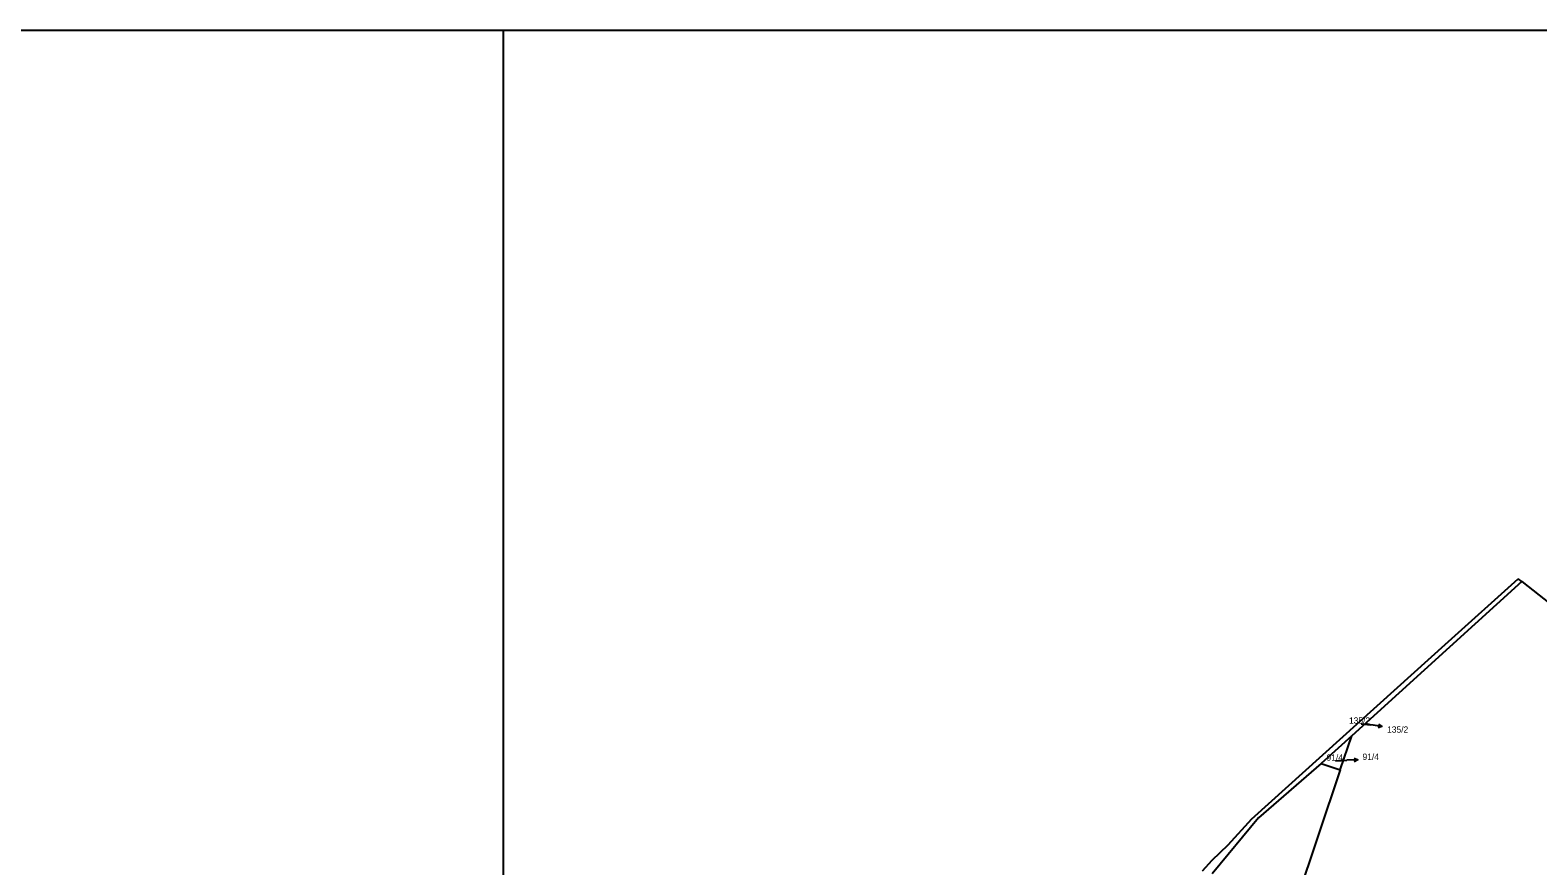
# Model space of a CAD drawing. Extents: x -752500 to -750336, y -1035826 to -1033500.
# Drawn here: x -752002.4 to -751596.3, y -1033725.2 to -1033500 of the extents above; entities that cross this region are included whole.
import ezdxf

# ---------------------------------------------------------------- set-up
doc = ezdxf.new("R2010")
doc.units = 0
for name, color, linetype in [('Default', 7, 'Continuous'), ('Hranice kat_území', 7, 'Continuous'), ('Hranice parcel', 7, 'Continuous'), ('ML1000', 7, 'Continuous'), ('Parcelní čísla', 7, 'Continuous'), ('Pop  PČ popisy', 7, 'Continuous')]:
    doc.layers.add(name, color=color, linetype=linetype)

# ---------------------------------------------------------------- blocks, each defined once
blk = doc.blocks.new('10292')
at = {"layer": 'Default'}
blk.add_line((0, 3), (0, 0), dxfattribs=at)
blk.add_lwpolyline([(-0.5, 2), (0, 3), (0.5, 2)], dxfattribs=at)

msp = doc.modelspace()

# ---------------------------------------------------------------- linework, layer by layer
at = {"layer": 'Hranice kat_území'}
for p, q in [((-751620.38, -1033664.69), (-751601.61, -1033647.82)), ((-751600.62, -1033648.57), (-751601.61, -1033647.82)), ((-751600.62, -1033648.57), (-751579.75, -1033664.94)), ((-751673.42, -1033712.57), (-751620.38, -1033664.69)), ((-751673.42, -1033712.57), (-751679.83, -1033719.58)), ((-751679.83, -1033719.58), (-751684.07, -1033723.74)), ((-751684.07, -1033723.74), (-751686.7, -1033726.57))]:
    msp.add_line(p, q, dxfattribs=at)
at = {"layer": 'Hranice parcel'}
for p, q in [((-751600.62, -1033648.57), (-751646.41, -1033690.12)), ((-751646.41, -1033690.12), (-751654.62, -1033697.57)), ((-751649.5, -1033699.28), (-751646.41, -1033690.12)), ((-751649.5, -1033699.28), (-751674.33, -1033773.12)), ((-751654.62, -1033697.57), (-751671.51, -1033712.21)), ((-751654.62, -1033697.57), (-751649.5, -1033699.28)), ((-751671.51, -1033712.21), (-751684.01, -1033727.32))]:
    msp.add_line(p, q, dxfattribs=at)
at = {"layer": 'ML1000'}
for points in [[(-752500, -1033500), (-751875, -1033500), (-751250, -1033500)], [(-751875, -1033500), (-751875, -1034000), (-751875, -1034500), (-751875, -1035000)]]:
    msp.add_lwpolyline(points, dxfattribs=at)
at = {"layer": 'Pop  PČ popisy'}
for p, q in [((-751643.86, -1033686.85), (-751641.24, -1033687.2)), ((-751650.8, -1033696.84), (-751647.74, -1033696.72))]:
    msp.add_line(p, q, dxfattribs=at)

# ---------------------------------------------------------------- block references
for p, rotation in [((-751641.24, -1033687.2), -97.52803400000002), ((-751647.74, -1033696.72), -87.84504700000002)]:
    msp.add_blockref('10292', p, dxfattribs=dict(at, rotation=rotation))

# ---------------------------------------------------------------- texts
at = {"layer": 'Parcelní čísla'}
for s, p in [('135/2', (-751647.15, -1033686.85)), ('135/2', (-751636.88, -1033689.29)), ('91/4', (-751653.2, -1033696.84)), ('91/4', (-751643.5, -1033696.61))]:
    msp.add_text(s, height=1.7, dxfattribs=at).set_placement(p)

doc.saveas('drawing.dxf')
